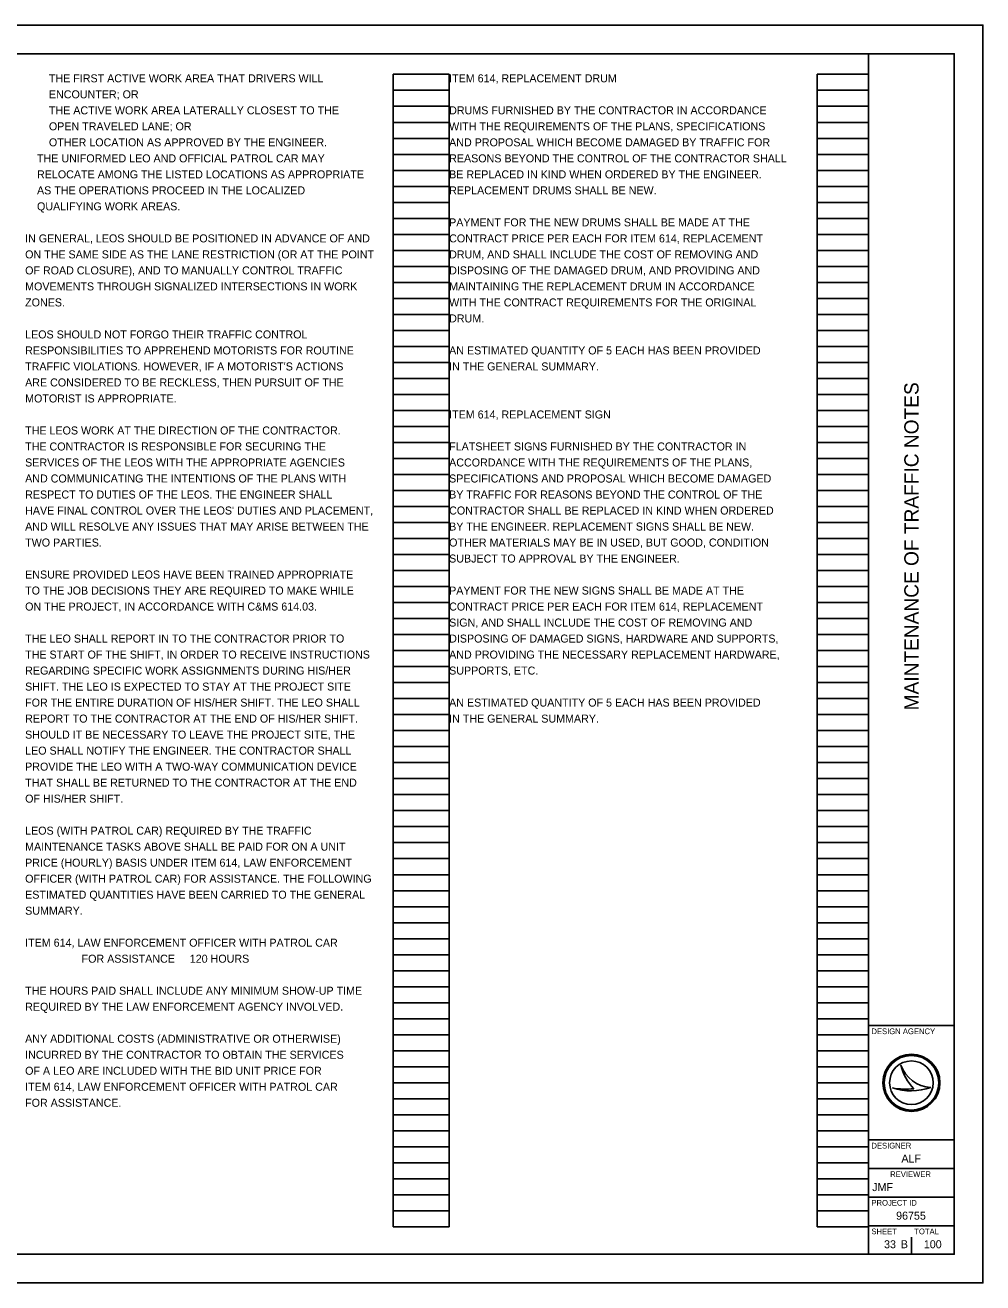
# Model space of a CAD drawing. Extents: x 0 to 34, y 0 to 22.
# Drawn here: x 17.24 to 34, y 0 to 22 of the extents above; entities that cross this region are included whole.
import ezdxf

# ---------------------------------------------------------------- set-up
doc = ezdxf.new("R2010")
doc.units = 0
for name, color, linetype in [('Default', 7, 'Continuous'), ('SH_Border', 7, 'Continuous'), ('SH_Cut_Line', 7, 'Continuous'), ('SH_Data', 7, 'Continuous'), ('SH_Text', 7, 'Continuous')]:
    doc.layers.add(name, color=color, linetype=linetype)

msp = doc.modelspace()

# ---------------------------------------------------------------- linework, layer by layer
at = {"layer": 'SH_Border'}
for p, q in [((32, 0.5), (32, 21.5)), ((32, 4.5), (33.5, 4.5)), ((32, 2.5), (33.5, 2.5)), ((32, 2), (33.5, 2)), ((32, 1.5), (33.5, 1.5)), ((32, 1), (33.5, 1))]:
    msp.add_line(p, q, dxfattribs=at)
msp.add_lwpolyline([(1.5, 21.5), (33.5, 21.5), (33.5, 0.5), (1.5, 0.5)], close=True, dxfattribs=at)
at = {"layer": 'SH_Cut_Line'}
msp.add_lwpolyline([(0, 0), (34, 0), (34, 22), (0, 22)], close=True, dxfattribs=at)
at = {"layer": 'SH_Data'}
for p, q in [((23.68, 0.98), (23.68, 21.14)), ((23.68, 21.14), (24.66, 21.14)), ((24.66, 0.98), (24.66, 21.14)), ((31.1, 0.98), (31.1, 21.14)), ((31.1, 21.14), (32, 21.14)), ((32, 0.98), (32, 21.14)), ((23.68, 20.86), (24.66, 20.86)), ((31.1, 20.86), (32, 20.86)), ((23.68, 20.58), (24.66, 20.58)), ((31.1, 20.58), (32, 20.58)), ((23.68, 20.3), (24.66, 20.3)), ((31.1, 20.3), (32, 20.3)), ((23.68, 20.02), (24.66, 20.02)), ((31.1, 20.02), (32, 20.02)), ((23.68, 19.74), (24.66, 19.74)), ((31.1, 19.74), (32, 19.74)), ((23.68, 19.46), (24.66, 19.46)), ((31.1, 19.46), (32, 19.46)), ((23.68, 19.18), (24.66, 19.18)), ((31.1, 19.18), (32, 19.18)), ((23.68, 18.9), (24.66, 18.9)), ((31.1, 18.9), (32, 18.9)), ((23.68, 18.62), (24.66, 18.62)), ((31.1, 18.62), (32, 18.62)), ((23.68, 18.34), (24.66, 18.34)), ((31.1, 18.34), (32, 18.34)), ((23.68, 18.06), (24.66, 18.06)), ((31.1, 18.06), (32, 18.06)), ((23.68, 17.78), (24.66, 17.78)), ((31.1, 17.78), (32, 17.78)), ((23.68, 17.5), (24.66, 17.5)), ((31.1, 17.5), (32, 17.5)), ((23.68, 17.22), (24.66, 17.22)), ((31.1, 17.22), (32, 17.22)), ((23.68, 16.94), (24.66, 16.94)), ((31.1, 16.94), (32, 16.94)), ((23.68, 16.66), (24.66, 16.66)), ((31.1, 16.66), (32, 16.66)), ((23.68, 16.38), (24.66, 16.38)), ((31.1, 16.38), (32, 16.38)), ((23.68, 16.1), (24.66, 16.1)), ((31.1, 16.1), (32, 16.1)), ((23.68, 15.82), (24.66, 15.82)), ((31.1, 15.82), (32, 15.82)), ((23.68, 15.54), (24.66, 15.54)), ((31.1, 15.54), (32, 15.54)), ((23.68, 15.26), (24.66, 15.26)), ((31.1, 15.26), (32, 15.26)), ((23.68, 14.98), (24.66, 14.98)), ((31.1, 14.98), (32, 14.98)), ((23.68, 14.7), (24.66, 14.7)), ((31.1, 14.7), (32, 14.7)), ((23.68, 14.42), (24.66, 14.42)), ((31.1, 14.42), (32, 14.42)), ((23.68, 14.14), (24.66, 14.14)), ((31.1, 14.14), (32, 14.14)), ((23.68, 13.86), (24.66, 13.86)), ((31.1, 13.86), (32, 13.86)), ((23.68, 13.58), (24.66, 13.58)), ((31.1, 13.58), (32, 13.58)), ((23.68, 13.3), (24.66, 13.3)), ((31.1, 13.3), (32, 13.3)), ((23.68, 13.02), (24.66, 13.02)), ((31.1, 13.02), (32, 13.02)), ((23.68, 12.74), (24.66, 12.74)), ((31.1, 12.74), (32, 12.74)), ((23.68, 12.46), (24.66, 12.46)), ((31.1, 12.46), (32, 12.46)), ((23.68, 12.18), (24.66, 12.18)), ((31.1, 12.18), (32, 12.18)), ((23.68, 11.9), (24.66, 11.9)), ((31.1, 11.9), (32, 11.9)), ((23.68, 11.62), (24.66, 11.62)), ((31.1, 11.62), (32, 11.62)), ((23.68, 11.34), (24.66, 11.34)), ((31.1, 11.34), (32, 11.34)), ((23.68, 11.06), (24.66, 11.06)), ((31.1, 11.06), (32, 11.06)), ((23.68, 10.78), (24.66, 10.78)), ((31.1, 10.78), (32, 10.78)), ((23.68, 10.5), (24.66, 10.5)), ((31.1, 10.5), (32, 10.5)), ((23.68, 10.22), (24.66, 10.22)), ((31.1, 10.22), (32, 10.22)), ((23.68, 9.94), (24.66, 9.94)), ((31.1, 9.94), (32, 9.94)), ((23.68, 9.66), (24.66, 9.66)), ((31.1, 9.66), (32, 9.66)), ((23.68, 9.38), (24.66, 9.38)), ((31.1, 9.38), (32, 9.38)), ((23.68, 9.1), (24.66, 9.1)), ((31.1, 9.1), (32, 9.1)), ((23.68, 8.82), (24.66, 8.82)), ((31.1, 8.82), (32, 8.82)), ((23.68, 8.54), (24.66, 8.54)), ((31.1, 8.54), (32, 8.54)), ((23.68, 8.26), (24.66, 8.26)), ((31.1, 8.26), (32, 8.26)), ((23.68, 7.98), (24.66, 7.98)), ((31.1, 7.98), (32, 7.98)), ((23.68, 7.7), (24.66, 7.7)), ((31.1, 7.7), (32, 7.7)), ((23.68, 7.42), (24.66, 7.42)), ((31.1, 7.42), (32, 7.42)), ((23.68, 7.14), (24.66, 7.14)), ((31.1, 7.14), (32, 7.14)), ((23.68, 6.86), (24.66, 6.86)), ((31.1, 6.86), (32, 6.86)), ((23.68, 6.58), (24.66, 6.58)), ((31.1, 6.58), (32, 6.58)), ((23.68, 6.3), (24.66, 6.3)), ((31.1, 6.3), (32, 6.3)), ((23.68, 6.02), (24.66, 6.02)), ((31.1, 6.02), (32, 6.02)), ((23.68, 5.74), (24.66, 5.74)), ((31.1, 5.74), (32, 5.74)), ((23.68, 5.46), (24.66, 5.46)), ((31.1, 5.46), (32, 5.46)), ((23.68, 5.18), (24.66, 5.18)), ((31.1, 5.18), (32, 5.18)), ((23.68, 4.9), (24.66, 4.9)), ((31.1, 4.9), (32, 4.9)), ((23.68, 4.62), (24.66, 4.62)), ((31.1, 4.62), (32, 4.62)), ((23.68, 4.34), (24.66, 4.34)), ((31.1, 4.34), (32, 4.34)), ((23.68, 4.06), (24.66, 4.06)), ((31.1, 4.06), (32, 4.06)), ((23.68, 3.78), (24.66, 3.78)), ((31.1, 3.78), (32, 3.78)), ((32.567, 3.81), (32.567, 3.81)), ((23.68, 3.5), (24.66, 3.5)), ((31.1, 3.5), (32, 3.5)), ((32.417, 3.41), (32.417, 3.41)), ((32.75, 3.5), (32.75, 3.5)), ((33.087, 3.419), (33.087, 3.419)), ((23.68, 3.22), (24.66, 3.22)), ((31.1, 3.22), (32, 3.22)), ((23.68, 2.94), (24.66, 2.94)), ((31.1, 2.94), (32, 2.94)), ((23.68, 2.66), (24.66, 2.66)), ((31.1, 2.66), (32, 2.66)), ((23.68, 2.38), (24.66, 2.38)), ((31.1, 2.38), (32, 2.38)), ((23.68, 2.1), (24.66, 2.1)), ((31.1, 2.1), (32, 2.1)), ((23.68, 1.82), (24.66, 1.82)), ((31.1, 1.82), (32, 1.82)), ((23.68, 1.54), (24.66, 1.54)), ((31.1, 1.54), (32, 1.54)), ((23.68, 1.26), (24.66, 1.26)), ((31.1, 1.26), (32, 1.26)), ((23.68, 0.98), (24.66, 0.98)), ((31.1, 0.98), (32, 0.98)), ((32.375, 0.675), (32.375, 0.675)), ((32.75, 0.5), (32.75, 0.8))]:
    msp.add_line(p, q, dxfattribs=at)
for radius in [0.5, 0.477, 0.477, 0.382]:
    msp.add_circle((32.75, 3.5), radius, dxfattribs=at)
for centre, radius, start, end in [((33.116, 3.998), 0.58, 198.9257, 198.9319), ((33.347, 3.97), 0.796, 191.6379, 191.6421), ((33.116, 3.998), 0.58, 198.9319, 267.1657), ((33.347, 3.97), 0.796, 191.6421, 226.0947), ((32.739, 4.37), 1.013, 251.4576, 290.0832), ((32.648, 4.654), 1.266, 259.4964, 259.4995), ((32.739, 4.37), 1.013, 251.4527, 251.4576), ((32.648, 4.654), 1.266, 259.4995, 276.6672)]:
    msp.add_arc(centre, radius, start, end, dxfattribs=at)
at = {"layer": 'SH_Text'}
msp.add_line((27.535, 21.032), (27.535, 21.032), dxfattribs=at)

# ---------------------------------------------------------------- texts
at = {"layer": 'Default'}
msp.add_text('B', height=0.14, dxfattribs=at).set_placement((32.564, 0.606))
at = {"layer": 'SH_Data'}
msp.add_text('MAINTENANCE OF TRAFFIC NOTES', height=0.25, rotation=90, dxfattribs=at).set_placement((32.875, 10.014))
for s, height, p in [('DESIGN AGENCY', 0.1, (32.05, 4.35)), ('DESIGNER', 0.1, (32.05, 2.35)), ('ALF', 0.14, (32.575, 2.105)), ('REVIEWER', 0.1, (32.378, 1.85)), ('JMF', 0.14, (32.064, 1.605)), ('PROJECT ID', 0.1, (32.05, 1.35)), ('96755', 0.14, (32.482, 1.105)), ('SHEET', 0.1, (32.05, 0.85)), ('TOTAL', 0.1, (32.8, 0.85)), ('33', 0.14, (32.271, 0.605)), ('100', 0.14, (32.967, 0.605))]:
    msp.add_text(s, height=height, dxfattribs=at).set_placement(p)
at = {"layer": 'SH_Text'}
for s, p in [('        THE FIRST ACTIVE WORK AREA THAT DRIVERS WILL', (17.24, 21)), ('ITEM 614, REPLACEMENT DRUM', (24.66, 21)), ('        ENCOUNTER; OR', (17.24, 20.72)), ('        THE ACTIVE WORK AREA LATERALLY CLOSEST TO THE', (17.24, 20.44)), ('DRUMS FURNISHED BY THE CONTRACTOR IN ACCORDANCE', (24.66, 20.44)), ('        OPEN TRAVELED LANE; OR', (17.24, 20.16)), ('WITH THE REQUIREMENTS OF THE PLANS, SPECIFICATIONS', (24.66, 20.16)), ('        OTHER LOCATION AS APPROVED BY THE ENGINEER.', (17.24, 19.88)), ('AND PROPOSAL WHICH BECOME DAMAGED BY TRAFFIC FOR', (24.66, 19.88)), ('    THE UNIFORMED LEO AND OFFICIAL PATROL CAR MAY', (17.24, 19.6)), ('REASONS BEYOND THE CONTROL OF THE CONTRACTOR SHALL', (24.66, 19.6)), ('    RELOCATE AMONG THE LISTED LOCATIONS AS APPROPRIATE', (17.24, 19.32)), ('BE REPLACED IN KIND WHEN ORDERED BY THE ENGINEER.', (24.66, 19.32)), ('    AS THE OPERATIONS PROCEED IN THE LOCALIZED', (17.24, 19.04)), ('REPLACEMENT DRUMS SHALL BE NEW.', (24.66, 19.04)), ('    QUALIFYING WORK AREAS.', (17.24, 18.76)), ('PAYMENT FOR THE NEW DRUMS SHALL BE MADE AT THE', (24.66, 18.48)), ('IN GENERAL, LEOS SHOULD BE POSITIONED IN ADVANCE OF AND', (17.24, 18.2)), ('CONTRACT PRICE PER EACH FOR ITEM 614, REPLACEMENT', (24.66, 18.2)), ('ON THE SAME SIDE AS THE LANE RESTRICTION (OR AT THE POINT', (17.24, 17.92)), ('DRUM, AND SHALL INCLUDE THE COST OF REMOVING AND', (24.66, 17.92)), ('OF ROAD CLOSURE), AND TO MANUALLY CONTROL TRAFFIC', (17.24, 17.64)), ('DISPOSING OF THE DAMAGED DRUM, AND PROVIDING AND', (24.66, 17.64)), ('MOVEMENTS THROUGH SIGNALIZED INTERSECTIONS IN WORK', (17.24, 17.36)), ('MAINTAINING THE REPLACEMENT DRUM IN ACCORDANCE', (24.66, 17.36)), ('ZONES.', (17.24, 17.08)), ('WITH THE CONTRACT REQUIREMENTS FOR THE ORIGINAL', (24.66, 17.08)), ('DRUM.', (24.66, 16.8)), ('LEOS SHOULD NOT FORGO THEIR TRAFFIC CONTROL', (17.24, 16.52)), ('RESPONSIBILITIES TO APPREHEND MOTORISTS FOR ROUTINE', (17.24, 16.24)), ('AN ESTIMATED QUANTITY OF 5 EACH HAS BEEN PROVIDED', (24.66, 16.24)), ("TRAFFIC VIOLATIONS. HOWEVER, IF A MOTORIST'S ACTIONS", (17.24, 15.96)), ('IN THE GENERAL SUMMARY.', (24.66, 15.96)), ('ARE CONSIDERED TO BE RECKLESS, THEN PURSUIT OF THE', (17.24, 15.68)), ('MOTORIST IS APPROPRIATE.', (17.24, 15.4)), ('ITEM 614, REPLACEMENT SIGN', (24.66, 15.12)), ('THE LEOS WORK AT THE DIRECTION OF THE CONTRACTOR.', (17.24, 14.84)), ('THE CONTRACTOR IS RESPONSIBLE FOR SECURING THE', (17.24, 14.56)), ('FLATSHEET SIGNS FURNISHED BY THE CONTRACTOR IN', (24.66, 14.56)), ('SERVICES OF THE LEOS WITH THE APPROPRIATE AGENCIES', (17.24, 14.28)), ('ACCORDANCE WITH THE REQUIREMENTS OF THE PLANS,', (24.66, 14.28)), ('AND COMMUNICATING THE INTENTIONS OF THE PLANS WITH', (17.24, 14)), ('SPECIFICATIONS AND PROPOSAL WHICH BECOME DAMAGED', (24.66, 14)), ('RESPECT TO DUTIES OF THE LEOS. THE ENGINEER SHALL', (17.24, 13.72)), ('BY TRAFFIC FOR REASONS BEYOND THE CONTROL OF THE', (24.66, 13.72)), ("HAVE FINAL CONTROL OVER THE LEOS' DUTIES AND PLACEMENT,", (17.24, 13.44)), ('CONTRACTOR SHALL BE REPLACED IN KIND WHEN ORDERED', (24.66, 13.44)), ('AND WILL RESOLVE ANY ISSUES THAT MAY ARISE BETWEEN THE', (17.24, 13.16)), ('BY THE ENGINEER. REPLACEMENT SIGNS SHALL BE NEW.', (24.66, 13.16)), ('TWO PARTIES.', (17.24, 12.88)), ('OTHER MATERIALS MAY BE IN USED, BUT GOOD, CONDITION', (24.66, 12.88)), ('SUBJECT TO APPROVAL BY THE ENGINEER.', (24.66, 12.6)), ('ENSURE PROVIDED LEOS HAVE BEEN TRAINED APPROPRIATE', (17.24, 12.32)), ('TO THE JOB DECISIONS THEY ARE REQUIRED TO MAKE WHILE', (17.24, 12.04)), ('PAYMENT FOR THE NEW SIGNS SHALL BE MADE AT THE', (24.66, 12.04)), ('ON THE PROJECT, IN ACCORDANCE WITH C&MS 614.03.', (17.24, 11.76)), ('CONTRACT PRICE PER EACH FOR ITEM 614, REPLACEMENT', (24.66, 11.76)), ('SIGN, AND SHALL INCLUDE THE COST OF REMOVING AND', (24.66, 11.48)), ('THE LEO SHALL REPORT IN TO THE CONTRACTOR PRIOR TO', (17.24, 11.2)), ('DISPOSING OF DAMAGED SIGNS, HARDWARE AND SUPPORTS,', (24.66, 11.2)), ('THE START OF THE SHIFT, IN ORDER TO RECEIVE INSTRUCTIONS', (17.24, 10.92)), ('AND PROVIDING THE NECESSARY REPLACEMENT HARDWARE,', (24.66, 10.92)), ('REGARDING SPECIFIC WORK ASSIGNMENTS DURING HIS/HER', (17.24, 10.64)), ('SUPPORTS, ETC.', (24.66, 10.64)), ('SHIFT. THE LEO IS EXPECTED TO STAY AT THE PROJECT SITE', (17.24, 10.36)), ('FOR THE ENTIRE DURATION OF HIS/HER SHIFT. THE LEO SHALL', (17.24, 10.08)), ('AN ESTIMATED QUANTITY OF 5 EACH HAS BEEN PROVIDED', (24.66, 10.08)), ('REPORT TO THE CONTRACTOR AT THE END OF HIS/HER SHIFT.', (17.24, 9.8)), ('IN THE GENERAL SUMMARY.', (24.66, 9.8)), ('SHOULD IT BE NECESSARY TO LEAVE THE PROJECT SITE, THE', (17.24, 9.52)), ('LEO SHALL NOTIFY THE ENGINEER. THE CONTRACTOR SHALL', (17.24, 9.24)), ('PROVIDE THE LEO WITH A TWO-WAY COMMUNICATION DEVICE', (17.24, 8.96)), ('THAT SHALL BE RETURNED TO THE CONTRACTOR AT THE END', (17.24, 8.68)), ('OF HIS/HER SHIFT.', (17.24, 8.4)), ('LEOS (WITH PATROL CAR) REQUIRED BY THE TRAFFIC', (17.24, 7.84)), ('MAINTENANCE TASKS ABOVE SHALL BE PAID FOR ON A UNIT', (17.24, 7.56)), ('PRICE (HOURLY) BASIS UNDER ITEM 614, LAW ENFORCEMENT', (17.24, 7.28)), ('OFFICER (WITH PATROL CAR) FOR ASSISTANCE. THE FOLLOWING', (17.24, 7)), ('ESTIMATED QUANTITIES HAVE BEEN CARRIED TO THE GENERAL', (17.24, 6.72)), ('SUMMARY.', (17.24, 6.44)), ('ITEM 614, LAW ENFORCEMENT OFFICER WITH PATROL CAR', (17.24, 5.88)), ('                   FOR ASSISTANCE     120 HOURS', (17.24, 5.6)), ('THE HOURS PAID SHALL INCLUDE ANY MINIMUM SHOW-UP TIME', (17.24, 5.04)), ('REQUIRED BY THE LAW ENFORCEMENT AGENCY INVOLVED.', (17.24, 4.76)), ('ANY ADDITIONAL COSTS (ADMINISTRATIVE OR OTHERWISE)', (17.24, 4.2)), ('INCURRED BY THE CONTRACTOR TO OBTAIN THE SERVICES', (17.24, 3.92)), ('OF A LEO ARE INCLUDED WITH THE BID UNIT PRICE FOR', (17.24, 3.64)), ('ITEM 614, LAW ENFORCEMENT OFFICER WITH PATROL CAR', (17.24, 3.36)), ('FOR ASSISTANCE.', (17.24, 3.08))]:
    msp.add_text(s, height=0.14, dxfattribs=at).set_placement(p)

doc.saveas('drawing.dxf')
